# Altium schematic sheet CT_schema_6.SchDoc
size 226 x 144 mm
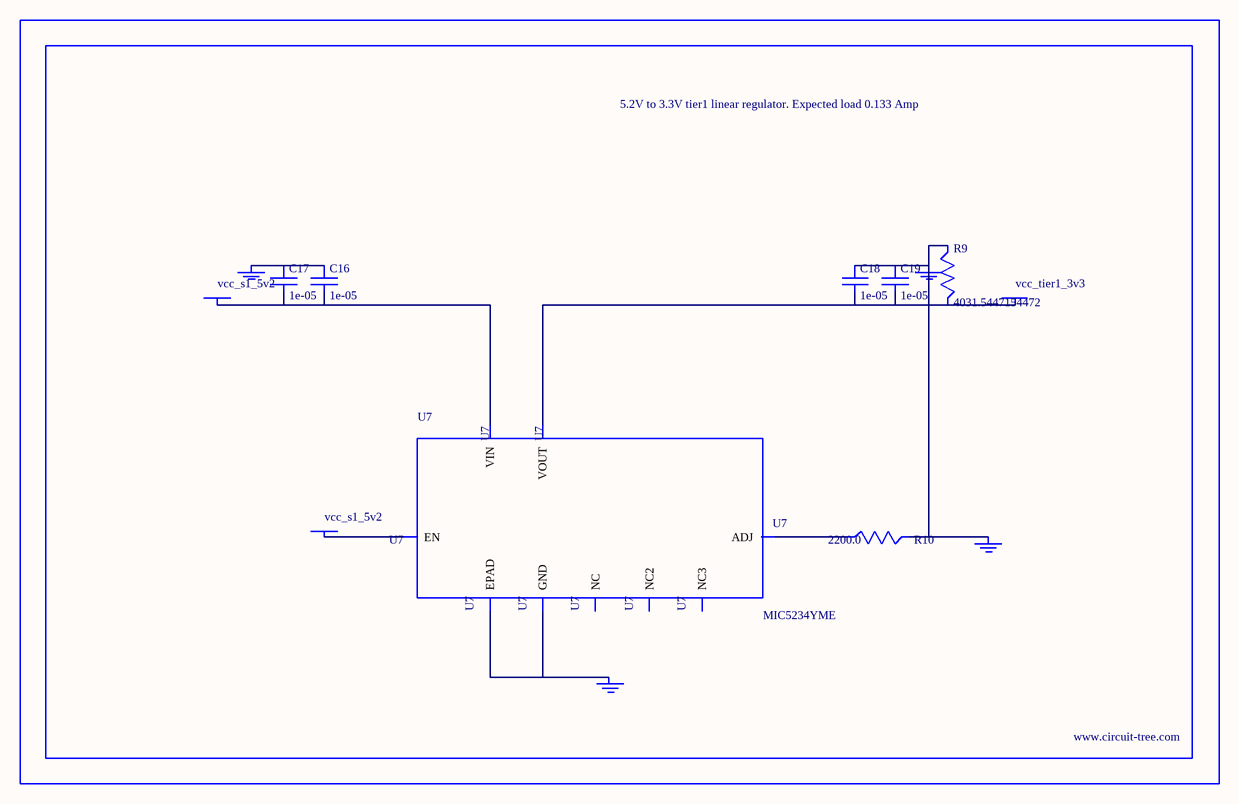
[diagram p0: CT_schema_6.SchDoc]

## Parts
BORDER5  (no value)
C16  1e-05  [C1210]
C17  1e-05  [C1210]
C18  1e-05  [C1210]
C19  1e-05  [C1210]
GND_INSTANCE_5_0  (no value)
GND_INSTANCE_5_1  (no value)
GND_INSTANCE_5_2  (no value)
GND_INSTANCE_5_3  (no value)
POWER_INSTANCE_5_0  vcc_tier1_3v3
POWER_INSTANCE_5_1  vcc_s1_5v2
POWER_INSTANCE_5_2  vcc_s1_5v2
R9  4031.5447154472  [R0603]
R10  2200.0  [R0603]
U7  MIC5234YME  [SOIC-8_EP]

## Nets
NetC16_1: C16.1 C17.1 GND_INSTANCE_5_3.0(GND)
NetC16_2: C16.2 C17.2 POWER_INSTANCE_5_2.0(PWR) U7.8(VIN)
NetC18_1: C18.1 C19.1 GND_INSTANCE_5_0.0(GND) GND_INSTANCE_5_1.0(GND) R9.1 R10.2
NetC18_2: C18.2 C19.2 POWER_INSTANCE_5_0.0(PWR) R9.2 U7.1(VOUT)
NetGND_INSTANCE_5_2_0: GND_INSTANCE_5_2.0(GND) U7.7(GND) U7.EPAD
NetPOWER_INSTANCE_5_1_0: POWER_INSTANCE_5_1.0(PWR) U7.5(EN)
NetR10_1: R10.1 U7.4(ADJ)

Not connected (* = marked no-connect by the designer): U7 2(NC) 3(NC2) 6(NC3)

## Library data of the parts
BORDER5 = BORDER_PAGE5
C16-C19 = C1210C106K5PACTU
GND_INSTANCE_5_0-GND_INSTANCE_5_3 = GND
POWER_INSTANCE_5_0-POWER_INSTANCE_5_2 = PWR
R9 = R9
R10 = RC0603JR-072K2L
